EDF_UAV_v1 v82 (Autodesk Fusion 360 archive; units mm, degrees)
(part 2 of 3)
sketch "Sketch36" plane through (50, 0, 0) normal (1, 0, 0) x axis (0, 1, 0)
  line L1 (17.5, -36.75) -> (-15, -36.75)
  line L2 (17.5, -4.25) -> (17.5, -36.75)
  line L3 (-15, -1.75) -> (15, -1.75)
  line L4 (-17.5, -34.25) -> (-17.5, -4.25)
  line L5 (13.2322, -6.0178) -> (-13.2322, -32.4822)
  line L6 (0, -19.25) -> (-13.2322, -6.0178)
  line L7 (-14.6464, -31.7751) -> (12.5251, -4.6036)
  line L8 (-12.5251, -33.8964) -> (14.6464, -6.7249)
  line L9 (-2.1213, -19.25) -> (-14.6464, -6.7249)
  line L10 (0, -17.1287) -> (-12.5251, -4.6036)
  line L11 (8.9645, -6.75) -> (13.4822, -2.2322)
  line L12 (-8.9645, -6.75) -> (8.9645, -6.75)
  line L13 (-13.4822, -2.2322) -> (-8.9645, -6.75)
  line L14 (-12.5, -10.2855) -> (-17.0178, -5.7678)
  line L15 (-12.5, -28.2145) -> (-12.5, -10.2855)
  line L16 (-17.0178, -32.7322) -> (-12.5, -28.2145)
  line L17 (-8.9645, -31.75) -> (-13.4822, -36.2678)
  line L18 (12.5, -31.75) -> (-8.9645, -31.75)
  line L19 (12.5, -10.2855) -> (12.5, -31.75)
  line L20 (17.0178, -5.7678) -> (12.5, -10.2855)
  arc A1 centre (-15, -34.25) radius 2.5 clockwise from (-17.5, -34.25) to (-15, -36.75)
  arc A2 centre (15, -4.25) radius 2.5 clockwise from (17.5, -4.25) to (15, -1.75)
  arc A3 centre (-15, -4.25) radius 2.5 clockwise from (-15, -1.75) to (-17.5, -4.25)
  arc A4 centre (15.25, -4) radius 2.5 clockwise from (17.0178, -5.7678) to (13.4822, -2.2322)
  arc A5 centre (-15.25, -4) radius 2.5 clockwise from (-13.4822, -2.2322) to (-17.0178, -5.7678)
  arc A6 centre (-15.25, -34.5) radius 2.5 clockwise from (-17.0178, -32.7322) to (-13.4822, -36.2678)
  point P12 (-13.2322, -32.4822)
  point P13 (13.2322, -6.0178)
  point P14 (-13.2322, -6.0178)
  point P15 (0, -19.25)
  point P16 (12.5251, -4.6036)
  point P17 (-14.6464, -31.7751)
  point P18 (14.6464, -6.7249)
  point P19 (-12.5251, -33.8964)
  point P20 (-14.6464, -6.7249)
  point P21 (-2.1213, -19.25)
  point P22 (-12.5251, -4.6036)
  point P23 (0, -17.1287)
  midpoint A1 P12
  midpoint A2 P13
  midpoint A3 P14
  midpoint L5 P15
  coincident A2 P16
  coincident A1 P17
  parallel L5 L7
  coincident A2 P18
  coincident A1 P19
  parallel L5 L8
  coincident A3 P20
  coincident L7 P21
  perpendicular L7 L9
  coincident A3 P22
  coincident L7 P23
  perpendicular L7 L10
  symmetric L5 L7 L8
  symmetric L6 L9 L10
  dimension "d637" distance L9 L10 = 3
  dimension "d638" distance L7 L8 = 3
extrude "Extrude29" add sketch "Sketch36" profile of A1 A2 A3 L7 L8 L9 L10 A4 A5 A6 along normal blind 1
fillet "Fillet5" radius 2
fillet "Fillet6" radius 3
mirror "Mirror14" mirrorStitchTolerance 0.1 bodies "pcb_holder_30.5x30.5 (1)"
work_plane "WorkPlane28"
sketch "Sketch41" plane through (-53.9267, 1.1626, -11.0386) normal (0.9795, -0.0211, 0.2005) x axis (0.0216, 0.9998, 0)
  line L1 (-11.6, -48.9705) -> (11.6, -48.9705)
  line L2 (-11.6, -72.1705) -> (-11.6, -48.9705)
  line L3 (11.6, -72.1705) -> (-11.6, -72.1705)
  line L4 (11.6, -48.9705) -> (11.6, -72.1705)
  line L5 (0, 22.0431) -> (0, 1.7145)
  point P2 (11.6, -48.9705)
  point P3 (-11.6, -48.9705)
  point P8 (-6.8004, -84.1705)
  horizontal L1
  vertical L2
  horizontal L3
  vertical L4
  equal L1 L2
  dimension "d662" distance P2 P3 = 23.2
  dimension "d663" distance L3 P8 = 12
extrude "Extrude30" cut sketch "Sketch41" profile of L1 L2 L3 L4 to an object
sketch "Sketch42" plane through (-53.9267, 1.1626, -11.0386) normal (0.9795, -0.0211, 0.2005) x axis (0.0216, 0.9998, 0)
  line L1 (-19.4, -44.0705) -> (31.6, -44.0705)
  line L2 (-19.4, -77.0705) -> (-19.4, -44.0705)
  line L3 (31.6, -77.0705) -> (-19.4, -77.0705)
  line L4 (31.6, -44.0705) -> (31.6, -77.0705)
  line L5 (-15.4, -48.0705) -> (27.6, -48.0705)
  line L6 (-15.4, -73.0705) -> (-15.4, -48.0705)
  line L7 (27.6, -73.0705) -> (-15.4, -73.0705)
  line L8 (27.6, -48.0705) -> (27.6, -73.0705)
  line L9 (-29.9, -98.0705) -> (33.1, -98.0705)
  line L10 (-28.9, -60.5705) -> (35.1, -60.5705)
  line L11 (0, 22.0431) -> (0, 1.7145)
  line L12 (-11.6, -72.1705) -> (-11.6, -48.9705)
  line L13 (11.6, -48.9705) -> (11.6, -72.1705)
  point P16 (-11.6, -48.9705)
  point P17 (-11.6, -72.1705)
  point P2 (31.6, -44.0705)
  point P3 (-19.4, -44.0705)
  point P7 (-15.4, -48.0705)
  point P8 (-15.4, -73.0705)
  horizontal L1
  vertical L2
  horizontal L3
  vertical L4
  horizontal L5
  vertical L6
  horizontal L7
  vertical L8
  horizontal L9
  horizontal L10
  symmetric L5 L7 L10
  symmetric L1 L3 L10
  symmetric L10 P16 P17
  dimension "d666" distance P2 P3 = 51
  dimension "d668" distance P7 P8 = 25
  dimension "d669" distance L1 L5 = 4
  dimension "d671" distance L4 L8 = 4
  dimension "d672" distance L4 L13 = 20
  dimension "d673" distance L2 L6 = 4
extrude "Extrude31" new body sketch "Sketch42" profile of L1 L2 L3 L4 L5 L6 L7 L8 to an object bodies "esc_base_adapter"
sketch "Sketch1" plane through (0, 0, 0) normal (1, 0, 0) x axis (0, 1, 0)
  line L1 (20.675, 11) -> (-20.675, 11)
  line L2 (20.675, -11) -> (20.675, 11)
  line L3 (-20.675, -11) -> (20.675, -11)
  line L4 (-20.675, 11) -> (-20.675, -11)
  line L5 (20.675, -11) -> (-20.675, 11)
  line L6 (-20.675, -11) -> (20.675, 11)
  point P6 (0, 0)
  point P1 (0, 0)
  point P4 (20.675, -11)
  point P5 (-20.675, -11)
  point P3 (20.675, 11)
  horizontal L1
  perpendicular L1 L2
  parallel L1 L3
  parallel L2 L4
  coincident L5 P6
  coincident L6 P6
  coincident P1 P6
  dimension "d713" distance P4 P5 = 41.35
  dimension "d714" distance P3 P4 = 22
extrude "Extrude1" new body sketch "Sketch1" profile of L1 L2 L3 L4 along normal blind 2.25
chamfer "Chamfer1" distance 2
sketch "Sketch2" plane through (0, 20.675, 0) normal (0, 1, 0) x axis (-1, 0, 0)
  line L1 (0, -9) -> (-2.25, -9)
  line L2 (0, 9) -> (0, -9)
  line L3 (-2.25, 9) -> (0, 9)
  line L4 (-2.25, -9) -> (-2.25, 9)
  line L5 (0, 9) -> (-2.25, 9)
  line L6 (0, 4) -> (0, 9)
  line L7 (-2.25, 4) -> (0, 4)
  line L8 (-2.25, 9) -> (-2.25, 4)
  line L9 (0, -9) -> (-2.25, -9)
  line L10 (0, -4) -> (0, -9)
  line L11 (-2.25, -4) -> (0, -4)
  line L12 (-2.25, -9) -> (-2.25, -4)
  point P8 (0, 4)
  point P5 (-2.25, 9)
  point P6 (-2.25, 9)
  point P12 (0, -4)
  point P2 (-2.25, -9)
  point P10 (-2.25, -9)
  point P9 (-2.25, 4)
  horizontal L5
  vertical L6
  horizontal L7
  vertical L8
  coincident L2 P8
  coincident P5 P6
  horizontal L9
  vertical L10
  horizontal L11
  vertical L12
  coincident L2 P12
  coincident P2 P10
  equal L8 L12
  dimension "d718" distance P6 P9 = 5
extrude "Extrude2" add sketch "Sketch2" along normal blind 5
sketch "Sketch3" plane through (0, -20.675, 0) normal (0, -1, 0) x axis (1, 0, 0)
  line L1 (2.25, -9) -> (0, -9)
  line L2 (2.25, 9) -> (2.25, -9)
  line L3 (0, 9) -> (2.25, 9)
  line L4 (0, -9) -> (0, 9)
  line L5 (2.25, 9) -> (0, 9)
  line L6 (2.25, 4) -> (2.25, 9)
  line L7 (0, 4) -> (2.25, 4)
  line L8 (0, 9) -> (0, 4)
  line L9 (2.25, 2.5) -> (0, 2.5)
  line L10 (2.25, -2.5) -> (2.25, 2.5)
  line L11 (0, -2.5) -> (2.25, -2.5)
  line L12 (0, 2.5) -> (0, -2.5)
  line L13 (2.25, -9) -> (0, -9)
  line L14 (2.25, -4) -> (2.25, -9)
  line L15 (0, -4) -> (2.25, -4)
  line L16 (0, -9) -> (0, -4)
  line L17 (22.5, 0) -> (1.75, 0)
  point P8 (2.25, 4)
  point P5 (0, 9)
  point P6 (0, 9)
  point P12 (2.25, -2.5)
  point P10 (0, 2.5)
  point P16 (2.25, -4)
  point P2 (0, -9)
  point P14 (0, -9)
  point P9 (0, 4)
  horizontal L5
  vertical L6
  horizontal L7
  vertical L8
  coincident L2 P8
  coincident P5 P6
  horizontal L9
  vertical L10
  horizontal L11
  vertical L12
  coincident L2 P12
  coincident L4 P10
  horizontal L13
  vertical L14
  horizontal L15
  vertical L16
  coincident L2 P16
  coincident P2 P14
  equal L8 L12
  equal L8 L16
  symmetric L9 L11 L17
  dimension "d721" distance P6 P9 = 5
extrude "Extrude3" add sketch "Sketch3" profile of L1 L2 L3 L4 L5 L6 L7 L8 L9 L10 L11 L12 L13 L14 L15 L16 along normal blind 5
joint "Assemble12" alignAngle -90 alignOffsetX -3.5 alignOffsetY -4 alignOffsetZ 0
sketch "Sketch61" plane through (-53.9267, 1.1626, -11.0386) normal (-0.9795, 0.0211, -0.2005) x axis (-0.0216, -0.9998, 0)
  line L1 (-27.6, -48.0705) -> (-27.6, -73.0705)
  line L2 (15.4, -48.0705) -> (-27.6, -48.0705)
  line L3 (15.4, -73.0705) -> (15.4, -48.0705)
  line L4 (-27.6, -73.0705) -> (15.4, -73.0705)
  line L5 (-31.6, -77.0705) -> (-31.6, -44.0705)
  line L6 (19.4, -77.0705) -> (-31.6, -77.0705)
  line L7 (19.4, -44.0705) -> (19.4, -77.0705)
  line L8 (-31.6, -44.0705) -> (19.4, -44.0705)
  line L9 (-29.1, -56.5705) -> (-27.6, -56.5705)
  line L10 (-29.1, -64.5705) -> (-29.1, -56.5705)
  line L11 (-27.6, -64.5705) -> (-29.1, -64.5705)
  line L12 (-27.6, -56.5705) -> (-27.6, -64.5705)
  line L13 (21.6967, -60.5705) -> (-33.7483, -60.5705)
  point P10 (-27.6, -56.5705)
  point P11 (-29.1, -56.5705)
  point P12 (-29.1, -64.5705)
  horizontal L9
  vertical L10
  horizontal L11
  vertical L12
  coincident L1 P10
  perpendicular L7 L13
  symmetric L6 L8 L13
  symmetric L9 L11 L13
  dimension "d808" distance P11 P12 = 8
  dimension "d809" distance L10 L12 = 1.5
extrude "Extrude54" cut sketch "Sketch61" profile of L1 L9 L10 L11 L12 to an object
work_plane "WorkPlane30"
sketch "Sketch51" plane through (0.1315, 6.0986, 0) normal (0.0216, 0.9998, 0) x axis (-0.2004, 0.0043, 0.9797)
  line L1 (-51.0705, -55.0572) -> (-44.0705, -55.0572)
  line L2 (-51.0705, -60.0572) -> (-51.0705, -55.0572)
  line L3 (-44.0705, -60.0572) -> (-51.0705, -60.0572)
  line L4 (-44.0705, -55.0572) -> (-44.0705, -60.0572)
  line L5 (-49.5705, -55.0572) -> (-49.5705, -57.3072)
  line L6 (-44.0705, -43.9534) -> (-44.0705, -55.0572)
  line L7 (-44.0705, -55.0572) -> (-77.0705, -55.0572)
  line L8 (-49.5705, -57.3072) -> (-51.5705, -57.3072)
  point P2 (-44.0705, -55.0572)
  point P5 (-44.0705, -60.0572)
  horizontal L1
  vertical L2
  horizontal L3
  vertical L4
  collinear L4 L6
  collinear L1 L7
  dimension "d736" distance L2 L5 = 1.5
  dimension "d812" distance P2 P5 = 5
extrude "Extrude41" new body sketch "Sketch51" profile of L1 L2 L3 L4 L7 to an object Side2Offset 0 bodies "esc_side_holder_long"
extrude "Extrude42" cut of existing geometry to an object
extrude "Extrude55" cut of existing geometry to an object
work_plane "WorkPlane31" AlongDistance -20
split_face "SplitFace1"
extrude "Extrude56" cut of existing geometry to an object
work_plane "WorkPlane32"
mirror "Mirror9" mirrorStitchTolerance 0.1 bodies "esc_side_holder_short"
offset_faces "OffsetFaces4" distance -0.1
offset_faces "OffsetFaces5" distance -0.1
split "Split3"
remove_body "RemoveBody1"
sketch "Sketch57" plane through (0.25, 11.5973, 0) normal (0.0216, 0.9998, 0) x axis (-0.9998, 0.0216, 0)
  line L1 (38.4871, -86.5442) -> (39.5898, -81.1558)
  line L2 (40.6915, -86.9953) -> (38.4871, -86.5442)
  line L3 (41.7942, -81.607) -> (40.6915, -86.9953)
  line L4 (39.5898, -81.1558) -> (41.7942, -81.607)
  line L5 (45.345, -87.9476) -> (46.7084, -81.2857)
  line L6 (41.8589, -80.2932) -> (41.5982, -81.5669)
  line L7 (46.7084, -81.2857) -> (41.8589, -80.2932)
  line L8 (43.3856, -87.5466) -> (38.4871, -86.5442)
  line L9 (44.4883, -82.1583) -> (43.3856, -87.5466)
  line L10 (39.5898, -81.1558) -> (44.4883, -82.1583)
  line L11 (38.4871, -86.5442) -> (39.5898, -81.1558)
  line L12 (43.3856, -87.5466) -> (45.345, -87.9476)
  line L13 (41.5982, -81.5669) -> (44.4883, -82.1583)
  line L14 (42.1951, -79.6476) -> (41.7942, -81.607)
  point P6 (46.7084, -81.2857)
  point P7 (46.7084, -81.2857)
  point P13 (43.3856, -87.5466)
  point P16 (43.3856, -87.5466)
  point P14 (44.4883, -82.1583)
  point P17 (44.4883, -82.1583)
  point P10 (41.5982, -81.5669)
  point P9 (41.5982, -81.5669)
  point P8 (45.345, -87.9476)
  coincident P6 P7
  perpendicular L5 L7
  coincident P13 P16
  perpendicular L9 L12
  coincident P14 P17
  perpendicular L9 L13
  coincident P10 L13
  coincident P9 P10
  dimension "d770" distance L4 L7 = 1.3
  dimension "d817" distance L6 L14 = 0.2
  dimension "d818" distance P8 P16 = 2
extrude "Extrude46" new body sketch "Sketch57" profile of L4 L5 L6 L7 L9 L10 L12 L13 L14 against normal blind 21 bodies "esc_clamp"
sketch "Sketch58" plane through (-60.783, 1.3104, -12.442) normal (-0.9795, 0.0211, -0.2005) x axis (-0.0216, -0.9998, 0)
  line L1 (9.4, -65.5705) -> (9.4, -77.0705)
  line L2 (-11.6, -65.5705) -> (9.4, -65.5705)
  line L3 (-11.6, -77.0705) -> (-11.6, -65.5705)
  line L4 (9.4, -77.0705) -> (-11.6, -77.0705)
  line L5 (-1.1, -76.5) -> (-1.1, -71.2594)
  line L6 (-9.2565, -74.3205) -> (-14.1927, -74.3205)
  line L7 (-31.6, -77.0705) -> (19.4, -77.0705)
  line L8 (-15.6, -71.5705) -> (-7.6, -71.5705)
  line L9 (-11.6, -77.0705) -> (-11.6, -70.2705)
  line L10 (9.4, -70.2705) -> (9.4, -77.0705)
  line L11 (-11.6, -70.2705) -> (9.4, -70.2705)
  line L12 (9.4, -77.0705) -> (-11.6, -77.0705)
  circle C1 centre (-1.1, -74.3205) radius 0.95
  circle C2 centre (-1.1, -74.3205) radius 1.1
  point P7 (-1.1, -74.3205)
  point P6 (-1.1, -74.3205)
  concentric C1 C2
  vertical L5
  coincident P7 L5
  horizontal L6
  coincident P6 L6
  dimension "d775" diameter C1 = 1.9
  dimension "d776" diameter C2 = 2.2
extrude "Extrude49" cut sketch "Sketch58" profile of C1 to an object
extrude "Extrude50" cut sketch "Sketch58" profile of C1 C2 to an object
mirror "Mirror10" mirrorStitchTolerance 0.1 bodies "esc_clamp2"
sketch "Sketch59" plane through (-60.783, 1.3104, -12.442) normal (-0.9795, 0.0211, -0.2005) x axis (-0.0216, -0.9998, 0)
  line L1 (-11.6, -50.8705) -> (-11.6, -44.0705)
  line L2 (9.4, -50.8705) -> (-11.6, -50.8705)
  line L3 (9.4, -44.0705) -> (9.4, -50.8705)
  line L4 (-11.6, -44.0705) -> (9.4, -44.0705)
  circle C1 centre (-1.1, -46.8205) radius 1.1
  circle C2 centre (-1.1, -46.8205) radius 0.95
  concentric C1 C2
  dimension "d796" diameter C2 = 1.9
extrude "Extrude51" cut sketch "Sketch59" profile of C2 to an object
sketch "Sketch1" plane through (0, 0, 0) normal (0, 1, 0) x axis (1, 0, 0)
  line L1 (-47, 35) -> (-49, 35)
  line L2 (-47, 45) -> (-47, 35)
  line L3 (-49, 45) -> (-47, 45)
  line L4 (-49, 35) -> (-49, 45)
  line L5 (47, 40) -> (-47, 40)
  point P6 (-47, 40)
  point P2 (-49, 35)
  point P5 (-49, 45)
  point P3 (-47, 35)
  horizontal L1
  vertical L2
  horizontal L3
  vertical L4
  coincident L2 P6
  symmetric L1 L3 L5
  dimension "d902" distance P2 P5 = 10
  dimension "d903" distance P2 P3 = 2
revolve "Revolve1" sketch "Sketch1" AlongAngle 360
chamfer "Chamfer2" distance 1.6 Rotate Angle 65
chamfer "Chamfer3" distance 1.6 Rotate Angle 65
work_plane "WorkPlane1" RotateAngle 0
sketch "Sketch2" plane through (0, -47, 0) normal (0, 1, 0) x axis (1, 0, 0)
  line L1 (-10, 40) -> (7, 40)
  line L2 (-47, 35) -> (47, 35)
  line L3 (-47, 45) -> (47, 45)
  line L4 (2.5, 35) -> (3.3816, 40)
  line L5 (-3.3816, 40) -> (-2.5, 35)
  line L6 (0, 49.5169) -> (0, 33.212)
  line L7 (0, -2.5) -> (0, -20)
  line L8 (-2.5, 35) -> (2.5, 35)
  line L9 (-3.3816, 40) -> (-2.5, 45)
  line L10 (2.5, 45) -> (3.3816, 40)
  line L11 (-2.5, 45) -> (2.5, 45)
  point P8 (3.3816, 40)
  point P9 (2.5, 35)
  point P10 (-2.5, 35)
  point P11 (-3.3816, 40)
  point P18 (3.3816, 40)
  point P17 (2.5, 45)
  point P19 (-2.5, 45)
  point P16 (-3.3816, 40)
  horizontal L1
  symmetric L1 L2 L3
  coincident L1 P8
  coincident L2 P9
  coincident L2 P10
  coincident L1 P11
  vertical L6
  collinear L6 L7
  symmetric L4 L5 L6
  symmetric L1 P8 P18
  symmetric L1 P9 P17
  symmetric L1 P10 P19
  symmetric L1 P11 P16
  dimension "d912" angle L5 L8 = 100
  dimension "d913" distance P9 P10 = 5
extrude "Extrude1" add sketch "Sketch2" profile of L2 L3 L4 L5 L8 L9 L10 L11 along normal blind 2
work_plane "WorkPlane2" RotateAngle 0
sketch "Sketch3" plane through (0, 47, 0) normal (0, -1, 0) x axis (-1, 0, 0)
  line L1 (-47, 35) -> (47, 35)
  line L2 (-47, 45) -> (47, 45)
  line L3 (0, -22.5) -> (0, -1.75)
  line L4 (-7, 40) -> (5, 40)
  line L5 (1, 35) -> (1.8816, 40)
  line L6 (-1.8816, 40) -> (-1, 35)
  line L7 (0, 48) -> (0, 32.5321)
  line L8 (-1, 35) -> (1, 35)
  line L9 (1, 45) -> (1.8816, 40)
  line L10 (-1, 45) -> (1, 45)
  line L11 (-1.8816, 40) -> (-1, 45)
  point P10 (1.8816, 40)
  point P11 (1, 35)
  point P12 (-1, 35)
  point P13 (-1.8816, 40)
  point P16 (1.8816, 40)
  point P17 (1, 45)
  point P18 (-1, 45)
  point P19 (-1.8816, 40)
  horizontal L4
  symmetric L1 L2 L4
  coincident L4 P10
  coincident L1 P11
  coincident L1 P12
  coincident L4 P13
  perpendicular L4 L7
  collinear L3 L7
  symmetric L5 L6 L7
  symmetric L4 P10 P16
  symmetric L4 P11 P17
  symmetric L4 P12 P18
  symmetric L4 P13 P19
  dimension "d918" angle L1 L6 = 100
  dimension "d919" distance P11 P12 = 2
extrude "Extrude2" add sketch "Sketch3" profile of L1 L2 L5 L6 L8 L9 L10 L11 along normal blind 2
work_plane "WorkPlane34" RotateAngle -45
sketch "Sketch65" plane through (-33.234, -33.234, 0) normal (-0.7071, -0.7071, 0) x axis (-0.7071, 0.7071, 0)
  line L1 (2.55, 45.2) -> (3.4669, 40)
  line L2 (-2.55, 45.2) -> (2.55, 45.2)
  line L3 (-3.4669, 40) -> (-2.55, 45.2)
  line L4 (3.4669, 40) -> (-3.4669, 40)
  line L5 (0, -22.5) -> (0, -1.75)
  line L6 (-47, 40) -> (47, 40)
  point P3 (2.55, 45.2)
  point P4 (-2.55, 45.2)
  horizontal L2
  parallel L2 L4
  symmetric L1 L3 L5
  collinear L4 L6
  dimension "d924" angle L3 L6 = 100
  dimension "d925" distance P3 P4 = 5.1
  dimension "d926" distance L2 L4 = 5.2
extrude "Extrude59" cut sketch "Sketch65" profile of L1 L2 L3 L4 L6 to an object
work_plane "WorkPlane35" RotateAngle 0
sketch "Sketch66" plane through (0, -47, 0) normal (0, -1, 0) x axis (-1, 0, 0)
  line L1 (2.55, 34.8) -> (3.4669, 40)
  line L2 (-2.55, 34.8) -> (2.55, 34.8)
  line L3 (-3.4669, 40) -> (-2.55, 34.8)
  line L4 (3.4669, 40) -> (-3.4669, 40)
  line L5 (0, -22.5) -> (0, -1.75)
  line L6 (-47, 40) -> (30.692, 40)
  point P3 (2.55, 34.8)
  point P4 (-2.55, 34.8)
  horizontal L2
  parallel L2 L4
  symmetric L1 L3 L5
  collinear L4 L6
  dimension "d930" distance L2 L4 = 5.2
  dimension "d931" angle L3 L6 = 100
  dimension "d932" distance P3 P4 = 5.1
extrude "Extrude60" cut sketch "Sketch66" profile of L1 L2 L3 L4 L6 to an object
work_plane "WorkPlane36" RotateAngle 45
sketch "Sketch67" plane through (33.234, 33.234, 0) normal (0.7071, 0.7071, 0) x axis (0.7071, -0.7071, 0)
  line L1 (47, 40) -> (-47, 40)
  line L2 (0, -22.5) -> (0, -1.75)
  line L3 (1.05, 45.2) -> (1.9669, 40)
  line L4 (-1.05, 45.2) -> (1.05, 45.2)
  line L5 (-1.9669, 40) -> (-1.05, 45.2)
  line L6 (1.9669, 40) -> (-1.9669, 40)
  point P7 (1.05, 45.2)
  point P8 (-1.05, 45.2)
  parallel L1 L4
  parallel L4 L6
  symmetric L2 L3 L5
  collinear L1 L6
  dimension "d936" distance L4 L6 = 5.2
  dimension "d937" angle L3 L6 = 100
  dimension "d938" distance P7 P8 = 2.1
extrude "Extrude61" cut sketch "Sketch67" profile of L1 L3 L4 L5 L6 to an object
circular_pattern "C-Pattern9" TotalAngle 180
work_plane "WorkPlane37" RotateAngle 0
sketch "Sketch68" plane through (0, 47, 0) normal (0, 1, 0) x axis (1, 0, 0)
  line L1 (1.05, 34.8) -> (1.9669, 40)
  line L2 (-1.05, 34.8) -> (1.05, 34.8)
  line L3 (-1.9669, 40) -> (-1.05, 34.8)
  line L4 (1.9669, 40) -> (-1.9669, 40)
  line L5 (0, -22.5) -> (0, -1.75)
  line L6 (-47, 40) -> (-34.5957, 40)
  line L7 (30.8016, 40) -> (31.8141, 40)
  line L8 (34.5957, 40) -> (47, 40)
  line L9 (-30.692, 40) -> (31.8141, 40)
  line L10 (-31.8141, 40) -> (30.8016, 40)
  point P4 (1.05, 34.8)
  point P5 (-1.05, 34.8)
  parallel L2 L4
  symmetric L1 L3 L5
  dimension "d943" distance P4 P5 = 2.1
  dimension "d944" distance L2 L4 = 5.2
extrude "Extrude62" cut sketch "Sketch68" profile of L1 L2 L3 L4 to an object
circular_pattern "C-Pattern10" TotalAngle 180
work_plane "WorkPlane1" RotateAngle -55
sketch "Sketch1" plane through (38.2954, 26.8147, 0) normal (0.8192, 0.5736, 0) x axis (0.5736, -0.8192, 0)
  line L1 (-8.5, -34) -> (8.5, -34)
  line L2 (-8.5, -24) -> (-8.5, -34)
  line L3 (8.5, -24) -> (-8.5, -24)
  line L4 (8.5, -34) -> (8.5, -24)
  line L5 (0, -22.5) -> (0, -1.75)
  line L6 (-48.8, -4) -> (4.1393, -4)
  point P2 (8.5, -34)
  point P3 (-8.5, -34)
  point P5 (8.5, -24)
  horizontal L1
  vertical L2
  horizontal L3
  vertical L4
  symmetric L2 L4 L5
  dimension "d959" distance P2 P3 = 17
  dimension "d960" distance P2 P5 = 10
  dimension "d961" distance L3 L6 = 20
extrude "Extrude1" new body sketch "Sketch1" profile of L1 L2 L3 L4 to an object second side blind -2
sketch "Sketch2" plane through (39.9337, 27.9619, 0) normal (0.8192, 0.5736, 0) x axis (-0.5736, 0.8192, 0)
  line L1 (8.5, 24) -> (-8.5, 24)
  line L2 (8.5, 34) -> (8.5, 24)
  line L3 (-8.5, 34) -> (8.5, 34)
  line L4 (-8.5, 34) -> (8.5, 34)
  line L5 (-8.5, 24) -> (-8.5, 34)
  line L6 (8.5, 24) -> (-8.5, 24)
  line L7 (8.5, 34) -> (8.5, 24)
  line L8 (-8.5, 24) -> (-8.5, 34)
  line L9 (8.5, 24) -> (-8.5, 24)
  line L10 (8.5, 34) -> (8.5, 24)
  line L11 (-8.5, 34) -> (8.5, 34)
  line L12 (-8.5, 24) -> (-8.5, 34)
  point P5 (8.5, 34)
  point P6 (8.5, 34)
  point P8 (-8.5, 24)
  point P10 (-8.5, 24)
  horizontal L4
  vertical L5
  horizontal L6
  vertical L7
  coincident P5 P6
  coincident P8 P10
extrude "Extrude2" new body sketch "Sketch2" along normal blind 13
sketch "Sketch3" plane through (4.8754, -6.9628, 0) normal (0.5736, -0.8192, 0) x axis (0.8192, 0.5736, 0)
  line L1 (45.9708, 24) -> (45.9708, 34)
  line L2 (48.75, 24) -> (45.9708, 24)
  line L3 (61.75, 34) -> (61.75, 24)
  line L4 (45.9708, 34) -> (48.75, 34)
  line L5 (61.75, 26.4944) -> (48.75, 34)
  line L6 (48.75, 34) -> (48.75, 24)
  line L7 (48.75, 24) -> (48.75, 34)
  line L8 (61.75, 24) -> (48.75, 24)
  line L9 (48.75, 34) -> (61.75, 34)
  point P6 (48.75, 34)
  point P7 (61.75, 26.4944)
  point P5 (48.75, 34)
  coincident L4 P6
  coincident L3 P7
  coincident P5 P6
  dimension "d966" angle L4 L5 = 30
extrude "Extrude3" cut sketch "Sketch3" profile of L3 L4 L5 to an object
sketch "Sketch4" plane through (22.0433, 15.4349, 46.6094) normal (0.4096, 0.2868, 0.866) x axis (-0.5736, 0.8192, 0)
  line L1 (8.5, -25.2187) -> (8.5, -40.2298)
  line L2 (-8.5, -40.2298) -> (-8.5, -25.2187)
  line L3 (8.5, -40.2298) -> (-8.5, -40.2298)
  line L4 (6, -37.2298) -> (-6, -37.2298)
  line L5 (0, -38.9469) -> (0, -32.4412)
  line L6 (-2.75, -37.2298) -> (-2.75, -40.2298)
  line L7 (2.75, -40.2298) -> (2.75, -37.2298)
  line L8 (-2.75, -40.2298) -> (-8.5, -40.2298)
  line L9 (8.5, -40.2298) -> (2.75, -40.2298)
  line L10 (-8.5, -42.2298) -> (-8.5, -40.2298)
  line L11 (8.5, -42.2298) -> (-8.5, -42.2298)
  line L12 (8.5, -40.2298) -> (8.5, -42.2298)
  line L13 (-8.5, -25.2187) -> (8.5, -25.2187)
  circle C1 centre (-6, -37.2298) radius 0.9
  circle C2 centre (6, -37.2298) radius 0.9
  arc A1 centre (0, -37.2298) radius 2.75 clockwise from (-2.75, -37.2298) to (2.75, -37.2298)
  point P6 (-6, -37.2298)
  point P7 (-6, -37.2298)
  point P8 (6, -37.2298)
  point P9 (6, -37.2298)
  point P12 (-2.75, -37.2298)
  point P13 (2.75, -37.2298)
  point P5 (-8.5, -40.2298)
  point P15 (-8.5, -40.2298)
  point P16 (-2.75, -40.2298)
  point P17 (2.75, -40.2298)
  point P2 (8.5, -40.2298)
  point P18 (8.5, -40.2298)
  coincident P6 P7
  horizontal L4
  coincident P8 P9
  equal C1 C2
  vertical L5
  symmetric P6 P9 L5
  coincident L4 P12
  perpendicular L4 L6
  coincident L4 P13
  perpendicular L4 L7
  tangent L6 A1
  symmetric L5 L6 L7
  coincident P5 P15
  coincident L3 P16
  coincident L3 P17
  coincident P2 P18
  perpendicular L8 L10
  perpendicular L1 L11
  perpendicular L9 L12
  dimension "d971" diameter C1 = 1.8
  dimension "d972" distance P6 P9 = 12
  dimension "d975" distance L6 L7 = 5.5
  dimension "d977" distance L3 L4 = 3
  dimension "d978" distance L9 L11 = 2
extrude "Extrude5" cut sketch "Sketch4" profile of L3 C1 C2 L6 L7 A1 L8 L9 L10 L11 L12 to an object
sketch "Sketch1" plane through (0, 0, 0) normal (1, 0, 0) x axis (0, 1, 0)
  line L1 (3.2, 0) -> (3.2, 30)
  line L2 (3.2, 0) -> (46.75, 0)
  line L3 (3.2, 30) -> (3.2, 0)
  line L4 (0, 30) -> (3.2, 30)
  line L5 (0, 0) -> (0, 30)
  line L6 (-46.75, 0) -> (0, 0)
  line L7 (0, 30) -> (0, 0)
  line L8 (0, 30) -> (3.2, 30)
  line L9 (-46.75, 63) -> (46.75, 63)
  curve K1 (-59.7, 62.2466) -> (-44.7, 63)
  line L10 (-48.75, 60) -> (-48.75, 62.4339)
  line L11 (-46.75, 60) -> (-48.75, 60)
  line L12 (44.7, 63) -> (-44.7, 63)
  line L13 (-46.75, 60) -> (-46.75, 63)
  line L14 (-44.7, 63) -> (-46.75, 63)
  line L15 (-59.7, 62.2466) -> (-57.7153, 62)
  curve K2 (-48.75, 62.4339) -> (-57.7153, 62)
  line L16 (-44.7, 55) -> (-44.7, 63)
  point P11 (-44.7, 63)
  point P16 (-44.7, 63)
  point P9 (-46.75, 63)
  point P19 (-46.75, 63)
  point P20 (-46.75, 63)
  point P22 (-44.7, 63)
  point P13 (-59.7, 62.2466)
  point P12 (-54, 78)
  point P10 (-46.75, 60)
  point P15 (-48.75, 60)
  point P18 (-57.7153, 62)
  coincident P11 P16
  coincident P9 P19
  coincident P9 P20
  vertical L13
  vertical L10
  horizontal L11
  coincident P16 P22
  perpendicular L14 L16
  dimension "d984" distance P11 P13 = 15
  dimension "d985" distance P11 P12 = 15
  dimension "d987" distance P10 P15 = 2
  dimension "d988" distance P13 P18 = 2
  dimension "d989" distance P15 P18 = 2
  dimension "d1002" distance L9 P18 = 1
revolve "Revolve1" sketch "Sketch1" AlongAngle 360
sketch "Sketch1" plane through (0, 0, 0) normal (0, 1, 0) x axis (1, 0, 0)
  line L1 (-20, -62) -> (20, -62)
  line L2 (-20, 28) -> (-20, -62)
  line L3 (20, -62) -> (20, 28)
  line L4 (0, -22.5) -> (0, -1.75)
  line L5 (-20, 28) -> (20, 28)
  line L6 (9.5, 33) -> (-9.5, 33)
  line L7 (-25, 33) -> (20.9676, 33)
  arc A1 centre (0, -9.5) radius 42.5 clockwise from (-20, 28) to (20, 28)
  point P2 (20, -62)
  point P3 (-20, -62)
  point P4 (-20, 28)
  horizontal L1
  vertical L2
  vertical L3
  symmetric L2 L3 L4
  horizontal L5
  tangent A1 L6
  parallel L6 L7
  tangent A1 L7
  dimension "d991" distance P2 P3 = 40
  dimension "d994" distance L1 L7 = 95
  dimension "d995" distance P4 L7 = 5
extrude "Extrude1" new body sketch "Sketch1" profile of L1 L2 L3 A1 along normal blind 32
joint "Assemble16" alignAngle 0 alignOffsetX -20 alignOffsetY 0 alignOffsetZ 0
copy_paste "CopyPaste1"
joint "Assemble17" alignAngle 180 alignOffsetX 20 alignOffsetY 0 alignOffsetZ 0
work_plane "WorkPlane1" RotateAngle -135
work_point "WorkPoint1" PathDistance 0.5002
work_plane "WorkPlane3" AlongDistance 46.2389
work_plane "WorkPlane6" AlongDistance 1
sketch "Sketch1" plane through (33.403, -33.403, 0) normal (0.7071, -0.7071, 0) x axis (0, 0, -1)
  line L1 (-110, 14.9881) -> (-115, 14.9881)
  line L2 (-110, -15.0119) -> (-110, 14.9881)
  line L3 (-115, -15.0119) -> (-110, -15.0119)
  line L4 (-115, 14.9881) -> (-115, -15.0119)
  line L5 (-90, -0.0119) -> (-115, -0.0119)
  line L6 (110, 14.9881) -> (115, 14.9881)
  line L7 (110, -15.0119) -> (110, 14.9881)
  line L8 (115, -15.0119) -> (110, -15.0119)
  line L9 (115, 14.9881) -> (115, -15.0119)
  line L10 (97, -0.0119) -> (115, -0.0119)
  point P6 (-115, -0.0119)
  point P7 (-115, -0.0119)
  point P13 (115, -0.0119)
  point P15 (115, -0.0119)
  point P2 (-115, 14.9881)
  point P3 (-110, 14.9881)
  point P4 (-110, -15.0119)
  point P9 (115, 14.9881)
  point P10 (110, 14.9881)
  point P11 (110, -15.0119)
  horizontal L1
  vertical L2
  horizontal L3
  vertical L4
  coincident L4 P6
  coincident P6 P7
  perpendicular L4 L5
  symmetric L1 L3 L5
  horizontal L6
  vertical L7
  horizontal L8
  vertical L9
  perpendicular L9 L10
  coincident P13 P15
  coincident L9 P13
  symmetric L6 L8 L10
  dimension "d1011" distance P2 P3 = 5
  dimension "d1012" distance P3 P4 = 30
  dimension "d1035" distance P9 P10 = 5
  dimension "d1036" distance P10 P11 = 30
extrude "Extrude1" new body sketch "Sketch1" profile of L6 L7 L8 L9 to an object
sketch "Sketch2" plane through (0, 0, -115) normal (0, 0, -1) x axis (1, 0, 0)
  line L1 (44.0012, 65.2312) -> (22.788, 44.018)
  line L2 (65.2144, 44.018) -> (44.0012, 65.2312)
  line L3 (44.0012, 22.8048) -> (65.2144, 44.018)
  line L4 (60.9717, 44.018) -> (44.0012, 60.9886)
  line L5 (44.0012, 27.0474) -> (60.9717, 44.018)
  line L6 (27.0306, 44.018) -> (44.0012, 27.0474)
  line L7 (44.0012, 60.9886) -> (27.0306, 44.018)
  line L8 (22.788, 44.018) -> (65.2144, 44.018)
  line L9 (44.0012, 22.8048) -> (44.0012, 65.2312)
  curve K1 (34.468, 23.099) -> (34.9359, 13.7395)
  line L10 (44.0012, 22.8048) -> (34.9359, 13.7395)
  line L11 (22.788, 44.018) -> (44.0012, 22.8048)
  line L12 (13.9182, 35.1482) -> (22.788, 44.018)
  curve K2 (13.9182, 35.1482) -> (23.099, 34.7027)
  curve K3 (31, 33.8552) -> (23.099, 34.7027)
  curve K4 (33.7634, 31) -> (31, 33.8552)
  curve K5 (34.468, 23.099) -> (33.7634, 31)
  circle C1 centre (60.9717, 44.018) radius 1.6
  circle C2 centre (44.0012, 60.9886) radius 1.6
  circle C3 centre (27.0306, 44.018) radius 1.6
  circle C4 centre (44.0012, 27.0474) radius 1.6
  point P6 (60.9717, 44.018)
  point P10 (60.9717, 44.018)
  point P8 (27.0306, 44.018)
  point P11 (27.0306, 44.018)
  point P7 (44.0012, 60.9886)
  point P12 (44.0012, 60.9886)
  point P9 (44.0012, 27.0474)
  point P13 (44.0012, 27.0474)
  point P14 (44.0012, 60.9886)
  point P15 (60.9717, 44.018)
  point P16 (44.0012, 27.0474)
  point P17 (27.0306, 44.018)
  point P5 (44.0012, 22.8048)
  point P18 (44.0012, 22.8048)
  point P21 (44.0012, 22.8048)
  point P2 (22.788, 44.018)
  point P22 (22.788, 44.018)
  point P4 (65.2144, 44.018)
  perpendicular L1 L2
  coincident P6 P10
  coincident P8 P11
  coincident P7 P12
  coincident P9 P13
  coincident P7 P14
  coincident P6 P15
  coincident P9 P16
  coincident P8 P17
  perpendicular L4 L5
  perpendicular L4 L7
  perpendicular L6 L7
  equal L4 L5
  equal C1 C4
  equal C1 C3
  equal C1 C2
  coincident P6 L8
  coincident P7 L9
  coincident P8 L8
  coincident P5 P18
  coincident P9 L9
  equal L8 L9
  perpendicular L2 L3
  coincident P5 P21
  coincident P2 P22
  dimension "d1022" distance P4 P5 = 30
  dimension "d1023" distance P6 P7 = 24
  dimension "d1024" diameter C1 = 3.2
extrude "Extrude2" add sketch "Sketch2" profile of L1 L2 L3 C1 C2 C3 C4 against normal blind 2
work_plane "WorkPlane4"
sketch "Sketch3" plane through (-0.0084, -0.0084, 0) normal (-0.7071, -0.7071, 0) x axis (0, 0, 1)
  line L1 (-113, 77.2389) -> (-110, 47.2389)
  point P2 (-113, 77.2389)
  point P3 (-113, 77.2389)
  point P5 (-110, 47.2389)
  point P6 (-110, 47.2389)
  coincident P2 P3
  coincident P5 P6
step "Rib" Thickness 3 DraftAngle 0 FilletRadius 0
fillet "Fillet1" radius 3
chamfer "Chamfer1" distance 9
fillet "Fillet4" radius 20
circular_pattern "C-Pattern1" TotalAngle 180
work_plane "WorkPlane1" RotateAngle -90
sketch "Sketch1" plane through (46.75, 0, 0) normal (1, 0, 0) x axis (0, 1, 0)
  line L1 (17.5, 32) -> (-17.5, 32)
  line L2 (17.5, 57) -> (17.5, 32)
  line L3 (-17.5, 57) -> (17.5, 57)
  line L4 (-17.5, 32) -> (-17.5, 57)
  line L5 (0, 22.5) -> (0, 1.75)
  line L6 (5.2, 30) -> (10.5704, 30)
  point P2 (-17.5, 32)
  point P3 (17.5, 32)
  point P5 (-17.5, 57)
  horizontal L1
  vertical L2
  horizontal L3
  vertical L4
  symmetric L2 L4 L5
  dimension "d856" distance P2 P3 = 35
  dimension "d857" distance P2 P5 = 25
  dimension "d955" distance L1 L6 = 2
extrude "Extrude1" new body sketch "Sketch1" profile of L1 L2 L3 L4 to an object second side blind -2
extrude "Extrude2" new body of existing geometry blind 20
sketch "Sketch3" plane through (0, 0, 57) normal (0, 0, 1) x axis (-1, 0, 0)
  line L1 (-48.75, 17.5) -> (-48.75, -17.5)
  line L2 (-68.75, 17.5) -> (-48.75, 17.5)
  line L3 (-68.75, -17.5) -> (-68.75, 17.5)
  line L4 (-48.75, -17.5) -> (-68.75, -17.5)
  line L5 (-50.75, 14) -> (-68.75, 14)
  line L6 (-50.75, -14) -> (-50.75, 14)
  line L7 (-68.75, -14) -> (-50.75, -14)
  line L8 (-68.75, 14) -> (-68.75, -14)
  line L9 (-50.0646, 0) -> (-72.5832, 0)
  point P6 (-68.75, 14)
  point P7 (-50.75, 14)
  point P8 (-50.75, -14)
  horizontal L5
  vertical L6
  horizontal L7
  vertical L8
  coincident L3 P6
  horizontal L9
  symmetric L2 L4 L9
  symmetric L5 L7 L9
  dimension "d868" distance P7 P8 = 28
  dimension "d869" distance L1 L6 = 2
extrude "Extrude4" cut sketch "Sketch3" profile of L3 L5 L6 L7 L8 to an object
sketch "Sketch4" plane through (0, 17.5, 0) normal (0, 1, 0) x axis (-1, 0, 0)
  line L1 (-48.75, 57) -> (-48.75, 32)
  line L2 (-68.75, 57) -> (-48.75, 57)
  line L3 (-68.75, 32) -> (-68.75, 57)
  line L4 (-48.75, 32) -> (-68.75, 32)
  line L5 (-45.4969, 44.5) -> (-72, 44.5)
  line L6 (-66.75, 32.4684) -> (-66.75, 53)
  circle C1 centre (-66.75, 44.5) radius 1.1
  arc A1 centre (-66.75, 44.5) radius 10.1 clockwise from (-57.7024, 48.9889) to (-62.2611, 35.4524)
  arc A2 centre (-62.75, 36.4377) radius 1.1 clockwise from (-62.2611, 35.4524) to (-63.2389, 37.4231)
  arc A3 centre (-66.75, 44.5) radius 7.9 clockwise from (-59.6731, 48.0111) to (-63.2389, 37.4231)
  arc A4 centre (-58.6877, 48.5) radius 1.1 clockwise from (-59.6731, 48.0111) to (-57.7024, 48.9889)
  arc A5 centre (-66.75, 44.5) radius 9 clockwise from (-58.6877, 48.5) to (-66.75, 35.5)
  point P6 (-66.75, 44.5)
  point P15 (-66.75, 44.5)
  point P14 (-66.75, 35.5)
  point P13 (-58.6877, 48.5)
  point P18 (-62.75, 36.4377)
  perpendicular L1 L5
  symmetric L2 L4 L5
  coincident P6 L5
  tangent A1 A2
  tangent A2 A3
  tangent A3 A4
  tangent A1 A4
  coincident P6 P15
  equal C1 A4
  perpendicular L5 L6
  coincident P15 L6
  coincident P14 L6
  dimension "d872" diameter C1 = 2.2
  dimension "d873" distance L3 P6 = 2
  dimension "d874" distance P6 P13 = 9
  dimension "d882" distance L6 P18 = 4
  dimension "d883" distance L5 P13 = 4
extrude "Extrude5" cut sketch "Sketch4" profile of C1 A1 A2 A3 A4 to an object
fillet "Fillet1" radius 10
fillet "Fillet2" radius 3
work_plane "WorkPlane2"
split "Split1"
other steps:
extrude "Extrude10" cut sketch "Sketch15" no distance stored
create_component "CreateComponent1"
create_component "CreateComponent2"
create_component "CreateComponent3"
joint_origin "JointOrigin6"
joint_origin "JointOrigin1"
create_component "CreateComponent4"
joint_origin "JointOrigin8"
joint_origin "JointOrigin9"
create_component "CreateComponent5"
joint_origin "JointOrigin2"
joint_origin "JointOrigin12"
joint_origin "JointOrigin8"
joint_origin "JointOrigin13"
joint_origin "JointOrigin13"
joint_origin "JointOrigin14"
joint_origin "JointOrigin15"
joint_origin "JointOrigin17"
create_component "CreateComponent7"
extrude "Extrude2" cut sketch "Sketch15" no distance stored
create_component "CreateComponent9"
create_component "CreateComponent10"
create_component "CreateComponent12"
joint_origin "JointOrigin1"
joint_origin "JointOrigin24"
joint_origin "JointOrigin4"
joint_origin "JointOrigin9"
joint_origin "JointOrigin25"
joint_origin "JointOrigin7"
joint_origin "JointOrigin11"
create_component "CreateComponent13"
create_component "CreateComponent17"
create_component "CreateComponent18"
create_component "CreateComponent19"
create_component "CreateComponent20"
joint_origin "JointOrigin1"
joint_origin "JointOrigin26"
joint_origin "JointOrigin3"
joint_origin "JointOrigin28"
create_component "CreateComponent21"
named bodies: "Body3 (1)", "Body4 (1)", "main_body_top", "pcb_holder_adapter", "battery_strap_loop", "battery_strap_loop2", "pcb_holder_adapter2", "battery_holder", "pcb_holder_30.5x30.5", "esc_base_adapter", "esc_side_holder_long", "esc_clamp", "esc_side_holder_short", "esc_clamp2", "main_body_bottom", "battery_strap_loop3", "battery_strap_loop4", "battery_holder (1)", "pcb_holder_30.5x30.5 (1)"

design "fin_mount"
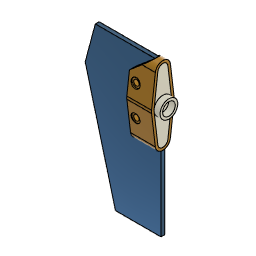
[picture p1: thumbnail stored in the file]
sketch "Sketch1" plane through (0, 0, 0) normal (1, 0, 0) x axis (0, 1, 0)
  line L1 (-1.9853, 12.6419) -> (-3.4743, 0.4234)
  line L2 (3.4743, 0.4234) -> (1.9853, 12.6419)
  line L3 (1.9853, -12.6419) -> (3.4743, -0.4234)
  line L4 (-3.4743, -0.4234) -> (-1.9853, -12.6419)
  line L5 (0, -85.5584) -> (0, 84.4416)
  line L6 (61.9831, 0) -> (-55, 0)
  line L7 (-3.5, -13.9728) -> (-3.5, 13.0272)
  line L8 (3.5, -12) -> (3.5, 11)
  line L9 (1.8303, 14.4) -> (-1.7707, 14.4)
  line L10 (2, -14.4) -> (-1.5, -14.4)
  arc A1 centre (0, 12.4) radius 2 clockwise from (-1.9853, 12.6419) to (1.9853, 12.6419)
  arc A2 centre (0, -12.4) radius 2 clockwise from (1.9853, -12.6419) to (-1.9853, -12.6419)
  arc A3 centre (0, 0) radius 3.5 clockwise from (-3.4743, -0.4234) to (-3.4743, 0.4234)
  arc A4 centre (0, 0) radius 3.5 clockwise from (3.4743, 0.4234) to (3.4743, -0.4234)
  point P1 (0, 0)
  vertical L5
  perpendicular L5 L6
  coincident P1 L5
  coincident P1 L6
  tangent L1 A1
  tangent L2 A1
  tangent L4 A2
  tangent L3 A2
  tangent L1 A3
  tangent L4 A3
  tangent L2 A4
  tangent L3 A4
  vertical L7
  tangent A3 L7
  equal A3 A4
  symmetric L3 L4 L5
  symmetric L1 L2 L5
  equal A1 A2
  symmetric L6 A1 A2
  equal L1 L4
  perpendicular L6 L8
  tangent A4 L8
  perpendicular L5 L9
  tangent A1 L9
  horizontal L10
  tangent A2 L10
  dimension "d2" radius A3 = 3.5
  dimension "d3" radius A1 = 2
  dimension "d4" distance L7 L8 = 7
  dimension "d5" distance L9 L10 = 28.8
extrude "Extrude1" new body sketch "Sketch1" profile of L1 L2 L3 L4 A1 A2 A3 A4 along normal blind 1.8
sketch "Sketch2" plane through (1.8, 0, 0) normal (1, 0, 0) x axis (0, 1, 0)
  line L1 (3.4743, -0.4234) -> (1.9853, -12.6419)
  line L2 (1.9853, 12.6419) -> (3.4743, 0.4234)
  line L3 (-3.4743, 0.4234) -> (-1.9853, 12.6419)
  line L4 (-1.9853, -12.6419) -> (-3.4743, -0.4234)
  arc A1 centre (0, -12.4) radius 2 clockwise from (1.9853, -12.6419) to (-1.9853, -12.6419)
  arc A2 centre (0, 0) radius 3.5 clockwise from (3.4743, 0.4234) to (3.4743, -0.4234)
  arc A3 centre (0, 12.4) radius 2 clockwise from (-1.9853, 12.6419) to (1.9853, 12.6419)
  arc A4 centre (0, 0) radius 3.5 clockwise from (-3.4743, -0.4234) to (-3.4743, 0.4234)
  circle C1 centre (0, 0) radius 3.5
  concentric A2 C1
  dimension "d8" diameter C1 = 7
extrude "Extrude2" add sketch "Sketch2" profile of A2 A4 C1 along normal blind 2.4
sketch "Sketch3" plane through (0, 0, 0) normal (-1, 0, 0) x axis (0, -1, 0)
  line L1 (3.4743, -0.4234) -> (1.9853, -12.6419)
  line L2 (1.9853, 12.6419) -> (3.4743, 0.4234)
  line L3 (-3.4743, 0.4234) -> (-1.9853, 12.6419)
  line L4 (-1.9853, -12.6419) -> (-3.4743, -0.4234)
  arc A1 centre (0, -12.4) radius 2 clockwise from (1.9853, -12.6419) to (-1.9853, -12.6419)
  arc A2 centre (0, 0) radius 3.5 clockwise from (3.4743, 0.4234) to (3.4743, -0.4234)
  arc A3 centre (0, 12.4) radius 2 clockwise from (-1.9853, 12.6419) to (1.9853, 12.6419)
  arc A4 centre (0, 0) radius 3.5 clockwise from (-3.4743, -0.4234) to (-3.4743, 0.4234)
  circle C1 centre (0, 0) radius 2.685
  circle C2 centre (0, 0) radius 2.175
  concentric A2 C1
  concentric C1 C2
  dimension "d11" diameter C1 = 5.37
  dimension "d12" diameter C2 = 4.35
extrude "Extrude3" add sketch "Sketch3" profile of C1 C2 along normal blind 0.5
hole "Hole1" HoleDepth 4.2 HoleDiameter 2.1 TipAngle 118
sketch "Sketch4" plane through (4.2, 0, 0) normal (1, 0, 0) x axis (0, 1, 0)
  circle C1 centre (0, 0) radius 1.05
  circle C2 centre (0, 0) radius 3.5
  circle C3 centre (0, 0) radius 2.5
  concentric C1 C3
  dimension "d18" diameter C3 = 5
extrude "Extrude4" cut sketch "Sketch4" profile of C1 C3 against normal blind 2.6
sketch "Sketch1" plane through (0, 0, 0) normal (-1, 0, 0) x axis (0, -1, 0)
  line L1 (1.9853, 12.6419) -> (3.4743, 0.4234)
  line L2 (-3.4743, 0.4234) -> (-1.9853, 12.6419)
  line L3 (-1.9853, -12.6419) -> (-3.4743, -0.4234)
  line L4 (3.4743, -0.4234) -> (1.9853, -12.6419)
  line L5 (-4.467, 0.5444) -> (-2.978, 12.7629)
  line L6 (-2.978, -12.7629) -> (-4.467, -0.5444)
  line L7 (4.467, -0.5444) -> (2.978, -12.7629)
  line L8 (2.978, 12.7629) -> (4.467, 0.5444)
  arc A1 centre (0, 12.4) radius 2 clockwise from (-1.9853, 12.6419) to (1.9853, 12.6419)
  arc A2 centre (0, 0) radius 3.5 clockwise from (-3.4743, -0.4234) to (-3.4743, 0.4234)
  arc A3 centre (0, -12.4) radius 2 clockwise from (1.9853, -12.6419) to (-1.9853, -12.6419)
  arc A4 centre (0, 0) radius 3.5 clockwise from (3.4743, 0.4234) to (3.4743, -0.4234)
  arc A5 centre (0, 0) radius 4.5 clockwise from (-4.467, -0.5444) to (-4.467, 0.5444)
  arc A6 centre (0, -12.4) radius 3 clockwise from (2.978, -12.7629) to (-2.978, -12.7629)
  arc A7 centre (0, 0) radius 4.5 clockwise from (4.467, 0.5444) to (4.467, -0.5444)
  arc A8 centre (0, 12.4) radius 3 clockwise from (-2.978, 12.7629) to (2.978, 12.7629)
  circle C1 centre (0, 0) radius 2.685
  circle C2 centre (0, 0) radius 2.885
  concentric C1 C2
  dimension "d83" = 1
  dimension "d116" distance C1 C2 = 0.2
  dimension "d98" AlongDistance = -1
  dimension "d99" TaperAngle = 0
  dimension "d104" Distance = 0.7
  dimension "d105" Rotate Angle = 45
extrude "Extrude2" new body sketch "Sketch1" profile of L1 A1 L2 A2 L3 A3 L4 A4 L8 A5 L5 L7 L6 A6 A7 A8 C2 along normal blind 8
sketch "Sketch4" plane through (-8, 0, 0) normal (-1, 0, 0) x axis (0, -1, 0)
  line L1 (-0.75, 15.4) -> (0.75, 15.4)
  line L2 (-0.75, -15.4) -> (-0.75, 15.4)
  line L3 (0.75, -15.4) -> (-0.75, -15.4)
  line L4 (0.75, 15.4) -> (0.75, -15.4)
  line L5 (-0.75, -15.4) -> (0.75, 15.4)
  line L6 (0.75, -15.4) -> (-0.75, 15.4)
  line L7 (-4.467, 0.5444) -> (-2.978, 12.7629)
  line L8 (-2.978, -12.7629) -> (-4.467, -0.5444)
  line L9 (4.467, -0.5444) -> (2.978, -12.7629)
  line L10 (2.978, 12.7629) -> (4.467, 0.5444)
  arc A1 centre (0, 12.4) radius 3 clockwise from (-2.978, 12.7629) to (2.978, 12.7629)
  arc A2 centre (0, 0) radius 4.5 clockwise from (-4.467, -0.5444) to (-4.467, 0.5444)
  arc A3 centre (0, -12.4) radius 3 clockwise from (2.978, -12.7629) to (-2.978, -12.7629)
  arc A4 centre (0, 0) radius 4.5 clockwise from (4.467, 0.5444) to (4.467, -0.5444)
  arc A5 centre (0, 12.4) radius 3 clockwise from (-2.978, 12.7629) to (2.978, 12.7629)
  circle C1 centre (0, 0) radius 2.885
  point P6 (0, 0)
  point P1 (0, 0)
  point P4 (-0.75, -15.4)
  point P5 (0.75, -15.4)
  horizontal L1
  perpendicular L1 L2
  parallel L1 L3
  parallel L2 L4
  coincident L5 P6
  coincident L6 P6
  coincident P1 P6
  tangent L1 A5
  dimension "d26" distance P4 P5 = 1.5
extrude "Extrude3" cut sketch "Sketch4" profile of L2 L4 to an object
sketch "Sketch7" plane through (-8, 0, 0) normal (-1, 0, 0) x axis (0, -1, 0)
  line L1 (-3.5, 8.4791) -> (-3.5, -8.4791)
  line L2 (-4.5, -15.3047) -> (-4.5, 15.3047)
  line L3 (0, 22.5) -> (0, 1.75)
  line L4 (-4.467, 0.5444) -> (-3.5584, 8)
  line L5 (-22.5, 0) -> (-1.75, 0)
  line L6 (-0.75, 15.3047) -> (-0.75, 2.7858)
  line L7 (-4.467, 0.5444) -> (-2.978, 12.7629)
  line L8 (-2.978, -12.7629) -> (-4.467, -0.5444)
  line L9 (-0.75, 15.3047) -> (-3.5, 8.4791)
  line L10 (-0.75, 15.3047) -> (-4.5, 15.3047)
  line L11 (-0.75, -15.3047) -> (-3.5, -8.4791)
  line L12 (-4.5, -15.3047) -> (-0.75, -15.3047)
  line L13 (0.75, -15.3047) -> (3.5, -8.4791)
  line L14 (4.5, -15.3047) -> (4.5, 15.3047)
  line L15 (0.75, 15.3047) -> (3.5, 8.4791)
  line L16 (4.5, -15.3047) -> (0.75, -15.3047)
  line L17 (4.467, 0.5444) -> (3.5584, 8)
  line L18 (0.75, 15.3047) -> (4.5, 15.3047)
  line L19 (3.5, 8.4791) -> (3.5, -8.4791)
  line L20 (-0.75, -2.7858) -> (-0.75, -15.3047)
  arc A1 centre (0, 0) radius 4.5 clockwise from (-4.467, -0.5444) to (-4.467, 0.5444)
  arc A2 centre (0, 12.4) radius 3 clockwise from (-2.978, 12.7629) to (-0.75, 15.3047)
  arc A3 centre (0, 0) radius 4.5 clockwise from (-4.467, -0.5444) to (-4.467, 0.5444)
  arc A4 centre (0, -12.4) radius 3 clockwise from (-0.75, -15.3047) to (-2.978, -12.7629)
  arc A5 centre (0, 0) radius 4.5 clockwise from (4.467, 0.5444) to (4.467, -0.5444)
  arc A6 centre (0, 0) radius 4.5 clockwise from (4.467, 0.5444) to (4.467, -0.5444)
  arc A7 centre (0, 0) radius 2.885 clockwise from (-0.75, -2.7858) to (-0.75, 2.7858)
  point P2 (-3.5, 8.4791)
  point P14 (-0.75, 15.3047)
  point P23 (-0.75, 15.3047)
  point P22 (-0.75, -15.3047)
  point P25 (-0.75, -15.3047)
  point P4 (-4.5, -15.3047)
  point P31 (3.5, 8.4791)
  point P3 (-3.5, -8.4791)
  point P30 (3.5, -8.4791)
  point P28 (4.5, -15.3047)
  point P5 (-4.467, 0.5444)
  point P35 (4.467, 0.5444)
  point P6 (-4.467, -0.5444)
  point P32 (4.467, -0.5444)
  point P10 (-3.5584, 8)
  point P33 (3.5584, 8)
  point P11 (-1.75, 0)
  point P39 (1.75, 0)
  point P17 (-4.467, 0.5444)
  point P38 (4.467, 0.5444)
  point P18 (-4.467, -0.5444)
  point P36 (4.467, -0.5444)
  point P34 (0.75, 15.3047)
  point P24 (-4.5, 15.3047)
  point P29 (4.5, 15.3047)
  point P37 (0.75, -15.3047)
  point P26 (-4.5, -15.3047)
  point P27 (4.5, -15.3047)
  tangent L2 A1
  vertical L1
  vertical L2
  coincident P2 L4
  coincident P14 P23
  perpendicular L6 L10
  coincident P22 P25
  perpendicular L2 L12
  coincident P4 L12
  symmetric P2 L3 P31
  symmetric P3 L3 P30
  symmetric P4 L3 P28
  symmetric P5 L3 P35
  symmetric P6 L3 P32
  symmetric A1 L3 A6
  symmetric L3 P10 P33
  symmetric L3 P11 P39
  symmetric L3 P17 P38
  symmetric L3 P18 P36
  symmetric L3 A3 A5
  symmetric L3 P23 P34
  symmetric L3 P24 P29
  symmetric L3 P25 P37
  symmetric L3 P26 P27
  dimension "d90" distance L1 L19 = 7
work_plane "WorkPlane4" AlongDistance -4.467
sketch "Sketch10" plane through (0, -4.467, 0) normal (0, 1, 0) x axis (1, 0, 0)
  line L1 (-8, -8.4791) -> (-8, 8.4791)
  line L2 (0, -8.4791) -> (-8, -8.4791)
  line L3 (-8, 8.4791) -> (0, 8.4791)
  line L4 (0, 8.4791) -> (0, -8.4791)
  line L5 (-8, -8.4791) -> (-8, 8.4791)
  line L6 (-1, -8.4791) -> (-8, -8.4791)
  line L7 (-1, 8.4791) -> (-1, -8.4791)
  line L8 (-8, 8.4791) -> (-1, 8.4791)
  point P4 (-5.2, -6)
  point P1 (0, 0)
  dimension "d54" distance L1 P4 = 2.8
  dimension "d112" distance P1 P4 = 6
hole "Hole1" HoleDepth 8.2691 HoleDiameter 2.2 TipAngle 118 CBDepth 1 CBDiameter 3.6
work_plane "WorkPlane5" AlongDistance 4.467
sketch "Sketch9" plane through (0, 4.467, 0) normal (0, 1, 0) x axis (-1, 0, 0)
  line L1 (8, 8.4791) -> (8, -8.4791)
  line L2 (3.25, 7.1258) -> (5.2, 8.2517)
  line L3 (3.25, 4.8742) -> (3.25, 7.1258)
  line L4 (5.2, 3.7483) -> (3.25, 4.8742)
  line L5 (7.15, 4.8742) -> (5.2, 3.7483)
  line L6 (7.15, 7.1258) -> (7.15, 4.8742)
  line L7 (5.2, 8.2517) -> (7.15, 7.1258)
  line L8 (1, 8.4791) -> (8, 8.4791)
  line L9 (1, -8.4791) -> (1, 8.4791)
  line L10 (8, -8.4791) -> (1, -8.4791)
  circle C1 centre (5.2, 6) radius 1.95
  circle C2 centre (5.2, 6) radius 1.1
  tangent C1 L2
  vertical L6
  dimension "d46" diameter C1 = 3.9
extrude "Extrude6" cut sketch "Sketch9" profile of L2 L3 L4 L5 L6 L7 against normal blind 1.3
mirror "Mirror1" mirrorStitchTolerance 0.1
ground "Ground1"
joint "Assemble3" alignAngle 0 alignOffsetX 0 alignOffsetY 0 alignOffsetZ 0
sketch "Sketch1" plane through (0, 0, 0) normal (0, 1, 0) x axis (1, 0, 0)
  line L1 (-26, -15) -> (0, -15)
  line L2 (-30, 0) -> (-26, -15)
  line L3 (-18, 45) -> (-30, 0)
  line L4 (0, 45) -> (-18, 45)
  line L5 (0, -15) -> (0, 45)
  line L6 (0, 0) -> (-30, 0)
  line L7 (-18, -45) -> (-30, 0)
  line L8 (0, -45) -> (-18, -45)
  line L9 (0, 0) -> (0, -45)
  point P1 (0, 0)
  point P7 (0, 0)
  point P10 (0, 0)
  point P2 (0, -15)
  point P6 (0, 45)
  point P5 (-18, 45)
  point P4 (-30, 0)
  point P9 (0, -45)
  horizontal L1
  parallel L1 L4
  perpendicular L1 L5
  coincident P1 L5
  coincident P1 P7
  horizontal L6
  horizontal L8
  coincident P1 P10
  perpendicular L6 L9
  parallel L2 L7
  equal L4 L8
  dimension "d1" distance P2 P6 = 60
  dimension "d2_1" distance P1 P6 = 45
  dimension "d3_1" distance P5 P6 = 18
  dimension "d5_1" distance P1 P4 = 30
  dimension "d8_1" distance P9 P10 = 45
extrude "Extrude1" new body sketch "Sketch1" profile of L1 L2 L3 L4 L5 distance 1.5 named "d9_1"
sketch "Sketch2" plane through (0, -0.75, 0) normal (0, -1, 0) x axis (1, 0, 0)
  line L1 (0, -45) -> (-18, -45)
  line L2 (0, 15) -> (0, -45)
  line L3 (-26, 15) -> (0, 15)
  line L4 (-30, 0) -> (-26, 15)
  line L5 (-18, -45) -> (-30, 0)
  line L6 (-2.3, 15) -> (0, 15)
  line L7 (-2.3, -15.7) -> (-2.3, 15)
  line L8 (0, -15.7) -> (-2.3, -15.7)
  line L9 (0, 15) -> (0, -15.7)
  point P1 (0, 0)
  point P11 (0, 15)
  point P9 (-2.3, -15.7)
  point P10 (0, -15.7)
  point P8 (-2.3, 15)
  horizontal L6
  vertical L7
  horizontal L8
  vertical L9
  coincident P1 L9
  coincident L6 P11
  dimension "d11_1" distance P9 P10 = 2.3
  dimension "d12_1" distance P8 P9 = 30.7
extrude "Extrude2" cut sketch "Sketch2" profile of L2 L3 L6 L7 L8 L9 no distance stored
joint "Assemble4" alignAngle 0 alignOffsetX 0 alignOffsetY 0 alignOffsetZ 0
extrude "Extrude7" add sketch "Sketch1" profile of L1 A1 L2 A2 L3 A3 L4 A4 L8 A5 L5 L7 L6 A6 A7 A8 against normal blind 1.8
sketch "Sketch11" plane through (0, 0, 0) normal (0, 1, 0) x axis (1, 0, 0)
  line L1 (-8, -9.0068) -> (-0.5, -15.3)
  line L2 (-8, -15.3) -> (-8, -9.0068)
  line L3 (-0.5, -15.3) -> (-8, -15.3)
  vertical L2
  perpendicular L2 L3
  dimension "d117" angle L1 L3 = 40
extrude "Extrude8" cut sketch "Sketch11" no distance stored
sketch "Sketch3" plane through (0, -0.75, 0) normal (0, -1, 0) x axis (1, 0, 0)
  line L1 (-2.3, 15) -> (-2.3, -15.7)
  line L2 (-26, 15) -> (-2.3, 15)
  line L3 (-30, 0) -> (-26, 15)
  line L4 (-18, -45) -> (-30, 0)
  line L5 (0, -45) -> (-18, -45)
  line L6 (0, -15.7) -> (0, -45)
  line L7 (-2.3, -15.7) -> (0, -15.7)
  circle C1 centre (-7, 5.6953) radius 1.1
  circle C2 centre (-7, -6.3047) radius 1.1
extrude "Extrude3" cut sketch "Sketch3" profile of C1 C2 no distance stored
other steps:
create_component "CreateComponent1"
create_component "CreateComponent2"
joint_origin "JointOrigin5"
joint_origin "JointOrigin6"
joint_origin "JointOrigin3"
create_component "CreateComponent3"

design "servo_savox_SH-0264MG"
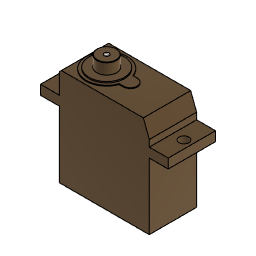
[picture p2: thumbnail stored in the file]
